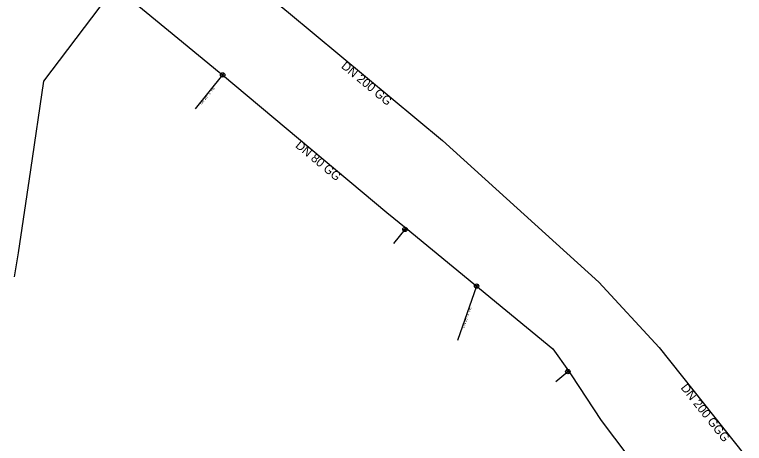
# Model space of a CAD drawing. Extents: x -482851 to -482354, y -1127969 to -1127406.
# Drawn here: x -482694.9 to -482560.7, y -1127634.2 to -1127555.4 of the extents above; entities that cross this region are included whole.
import ezdxf

# ---------------------------------------------------------------- set-up
doc = ezdxf.new("R2010")
doc.units = 0
for name, color, linetype in [('_pripojka_prevzato_z_dokumentace_', 7, 'Continuous'), ('_pripojka_priblizne_', 7, 'Continuous'), ('_voda_smvak_prevzato_z_dokumentace_', 7, 'Continuous'), ('Default', 7, 'Continuous'), ('MoLevel 32', 7, 'Continuous'), ('MoLevel 46', 7, 'Continuous'), ('MoLevel 53', 7, 'Continuous'), ('MoLevel 55', 7, 'Continuous')]:
    doc.layers.add(name, color=color, linetype=linetype)

# ---------------------------------------------------------------- blocks, each defined once
blk = doc.blocks.new('_uzaver_pripojka_')
at = {"layer": 'Default'}
for p, q in [((-0.000035, -0.000035), (0.000035, 0.000035)), ((0.000035, -0.000035), (-0.000035, 0.000035))]:
    blk.add_line(p, q, dxfattribs=at)
for radius in [0.00005, 0.0000025]:
    blk.add_circle((0, 0), radius, dxfattribs=at)

msp = doc.modelspace()

# ---------------------------------------------------------------- linework, layer by layer
at = {"layer": '_pripojka_prevzato_z_dokumentace_'}
for p, q in [((-482656.66, -1127566.46), (-482661.71, -1127572.67)), ((-482623.11, -1127594.87), (-482622.92, -1127594.63)), ((-482593.15, -1127621.02), (-482593.02, -1127620.91))]:
    msp.add_line(p, q, dxfattribs=at)
at = {"layer": '_pripojka_priblizne_'}
for p, q in [((-482625.18, -1127597.47), (-482623.11, -1127594.87)), ((-482609.95, -1127605.29), (-482613.47, -1127615.31)), ((-482595.38, -1127622.86), (-482593.15, -1127621.02))]:
    msp.add_line(p, q, dxfattribs=at)
at = {"layer": '_voda_smvak_prevzato_z_dokumentace_'}
msp.add_line((-482572.04, -1127621.97), (-482560.66, -1127636.35), dxfattribs=at)
for points in [[(-482694.95, -1127603.6), (-482694.23, -1127599.18), (-482691.97, -1127583.92), (-482689.56, -1127567.61), (-482679.18, -1127553.95), (-482676.4, -1127550.29), (-482673.12, -1127552.99), (-482664.93, -1127559.73), (-482657.29, -1127565.93), (-482656.66, -1127566.46), (-482626.44, -1127591.74), (-482622.92, -1127594.63), (-482595.91, -1127616.84), (-482593.02, -1127620.91), (-482592.52, -1127621.61), (-482587.02, -1127630.02), (-482572.11, -1127649.75), (-482571.27, -1127650.87), (-482568.88, -1127654.08), (-482563.8, -1127660.9)], [(-482650.53, -1127550), (-482649.94, -1127550.49), (-482644.56, -1127554.99), (-482616.22, -1127578.54), (-482587.42, -1127604.56), (-482576.33, -1127616.56), (-482572.3, -1127621.68), (-482572.04, -1127621.97)]]:
    msp.add_lwpolyline(points, dxfattribs=at)

# ---------------------------------------------------------------- block references
at = {"layer": 'MoLevel 53', "xscale": 7999.999999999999, "yscale": 7999.999999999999}
for p in [(-482656.66, -1127566.46), (-482609.95, -1127605.29), (-482593.15, -1127621.02)]:
    msp.add_blockref('_uzaver_pripojka_', p, dxfattribs=at)
at = {"layer": 'MoLevel 53', "xscale": 7999.999999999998, "yscale": 8000, "rotation": -128.47963611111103}
msp.add_blockref('_uzaver_pripojka_', (-482623.11, -1127594.87), dxfattribs=at)

# ---------------------------------------------------------------- texts
at = {"layer": 'MoLevel 32'}
msp.add_text("DN 25 - 1'' PE", height=0.455, rotation=70.6468, dxfattribs=at).set_placement((-482612.18, -1127612.99))
at = {"layer": 'MoLevel 46'}
for s, rotation, p in [('DN 200 GG', 320.2848, (-482634.97, -1127565.05)), ('DN 80 GG', 320.09, (-482643.4, -1127579.65)), ('DN 200 GGG', 308.3573, (-482572.46, -1127624.03))]:
    msp.add_text(s, height=1.605, rotation=rotation, dxfattribs=at).set_placement(p)
at = {"layer": 'MoLevel 55'}
msp.add_text("DN 25 - 1'' PE", height=0.455, rotation=50.8905, dxfattribs=at).set_placement((-482660.54, -1127571.96))

doc.saveas('drawing.dxf')
